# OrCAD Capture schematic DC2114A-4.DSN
size Custom; title: 42V, LOW I   QUAD OUTPUT TRIPLE MONOLITHIC; rev: 4; note: DC2114A; note: Q
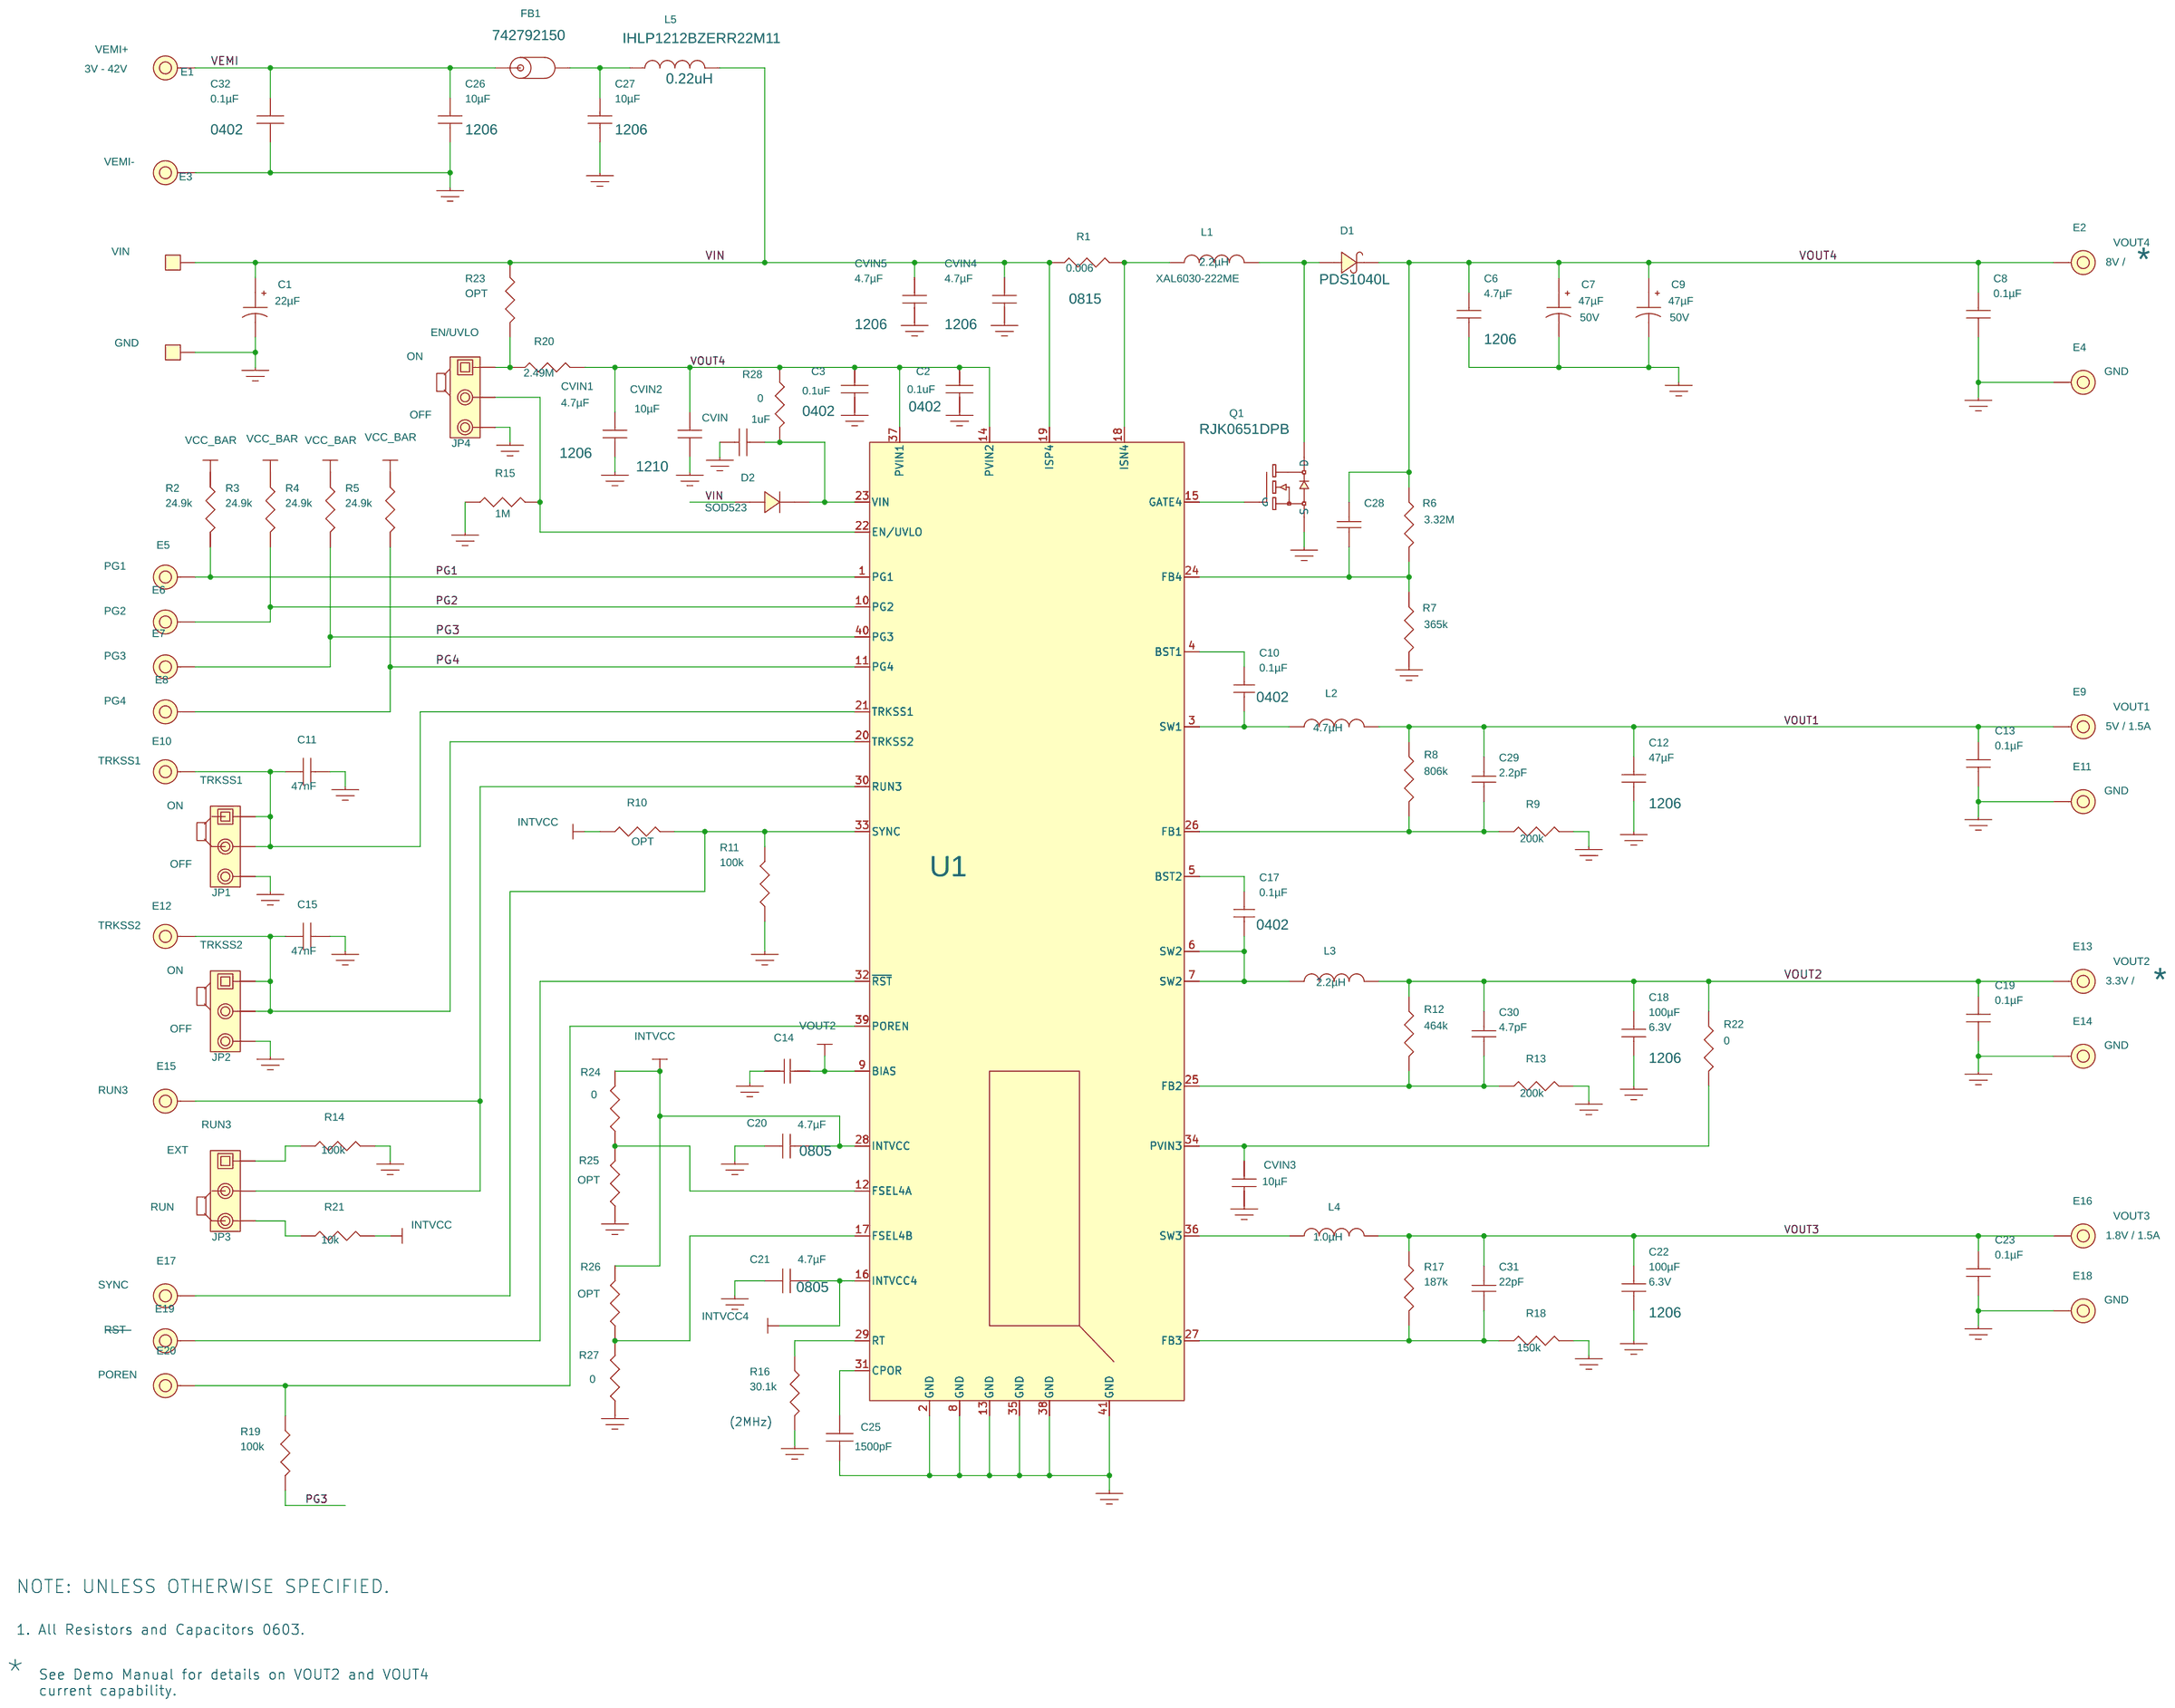
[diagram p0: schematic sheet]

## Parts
C1  22µF  [OSCON-CE-6.3]
C2  0.1uF  [0402]
C3  0.1uF  [0402]
C6  4.7µF  [1206]
C7  47µF  [OSCON-CE-6.3]
C8  0.1µF  [0603]
C9  47µF  [OSCON-CE-6.3]
C10  0.1µF  [0402]
C11  47nF  [0603]
C12  47µF  [1206]
C13  0.1µF  [0603]
C14  TBD  [0603]
C15  47nF  [0603]
C17  0.1µF  [0402]
C18  100µF  [1206]
C19  0.1µF  [0603]
C20  4.7µF  [0805]
C21  4.7µF  [0805]
C22  100µF  [1206]
C23  0.1µF  [0603]
C25  1500pF  [0603]
C26  10µF  [1206]
C27  10µF  [1206]
C28  TBD  [0603]
C29  2.2pF  [0603]
C30  4.7pF  [0603]
C31  22pF  [0603]
C32  0.1µF  [0402]
CVIN  1uF  [0603]
CVIN1  4.7µF  [1206]
CVIN2  10µF  [1210]
CVIN3  10µF  [0603]
CVIN4  4.7µF  [1206]
CVIN5  4.7µF  [1206]
D1  PDS1040L  [POWER-DI-5]
D2  SOD523  [SOD523]
E1  Testpoint  [0.094"]
E2  Testpoint  [0.094"]
E3  Testpoint  [0.094"]
E4  Testpoint  [0.094"]
E5  Testpoint  [0.094"]
E6  Testpoint  [0.094"]
E7  Testpoint  [0.094"]
E8  Testpoint  [0.094"]
E9  Testpoint  [0.094"]
E10  Testpoint  [0.094"]
E11  Testpoint  [0.094"]
E12  Testpoint  [0.094"]
E13  Testpoint  [0.094"]
E14  Testpoint  [0.094"]
E15  Testpoint  [0.094"]
E16  Testpoint  [0.094"]
E17  Testpoint  [0.094"]
E18  Testpoint  [0.094"]
E19  Testpoint  [0.094"]
E20  Testpoint  [0.094"]
FB1  742792150  [1206]
GND  Testpoint  [PAD30(SM)]
JP1  3 Pins 2mm Ctrs.  [Samtec\TMM-103-02-L-S]
JP2  3 Pins 2mm Ctrs.  [Samtec\TMM-103-02-L-S]
JP3  3 Pins 2mm Ctrs.  [Samtec\TMM-103-02-L-S]
JP4  3 Pins 2mm Ctrs.  [Samtec\TMM-103-02-L-S]
L1  2.2µH  [XAL6030-102ME-CBD/COILCRAFT]
L2  4.7µH  [IND-XAL50XX]
L3  2.2µH  [IND-XAL50XX]
L4  1.0µH  [NPIM42P]
L5  0.22uH  [IND-IHLP-1212AB-11]
Q1  60V/25A  [LFPAK/FET]
R1  0.006  [0815]
R2  24.9k  [0603]
R3  24.9k  [0603]
R4  24.9k  [0603]
R5  24.9k  [0603]
R6  3.32M  [0603]
R7  365k  [0603]
R8  806k  [0603]
R9  200k  [0603]
R10  TBD  [0603]
R11  100k  [0603]
R12  464k  [0603]
R13  200k  [0603]
R14  100k  [0603]
R15  1M  [0603]
R16  30.1k  [0603]
R17  187k  [0603]
R18  150k  [0603]
R19  100k  [0603]
R20  2.49M  [0603]
R21  10k  [0603]
R22  0  [0603]
R23  OPT  [0603]
R24  0  [0603]
R25  OPT  [0603]
R26  OPT  [0603]
R27  0  [0603]
R28  0  [0603]
U1  Buck Regulator  [QFN(40)(UJ)6MMX6MM]
VIN  Testpoint  [PAD30(SM)]
XJP1  2mm Ctrs.
XJP2  2mm Ctrs.
XJP3  2mm Ctrs.
XJP4  2mm Ctrs.

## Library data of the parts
C1 = 50CE22BSS: 4th Part Field: Sun Elect. Ind.
C2 C3 CVIN = C1608X5R1H105K
C6 = C3216X7R1H475KT_1
C7 = 50CE22BSS_2: 1st Part Field: 50V; 4th Part Field: Sun Elect. Ind.; 5TH PART FIELD: 50CE47BS
C8 C13 C19 C23 = GRM188R71H104KA93D
C9 = 50CE22BSS_1: 1st Part Field: 50V; 4th Part Field: Sun Elect. Ind.; 5TH PART FIELD: 25CE47BSS
C10 C17 = 06033C104KAT2A
C11 C15 = 06033C473MAT2A
C12 = GRM31CR61A476ME15L
C14 C28-C31 = CAP0603
C18 C22 = GRM31CR61A476ME15L: 1st Part Field: 6.3V
C20 C21 = GRM21BR71A475KA73K
C25 = 06033C221MAT2A: 2nd Part Field: 20%; 7th Part Field: Cap.,
C26 = C3216X7R1H475KT_5
C27 = C3216X7R1H475KT_3
C32 = CGA2B3X7R1H104K050BB
CVIN1 = C3216X7R1H475KT
CVIN2 = C3216X7R1H475KT_2
CVIN3 = GRM188R61E105KA12
CVIN4 = C3216X7R1H475KT_4
CVIN5 = C3216X7R1H475KT_6
D1 = B540C_0
D2 = diode-photo_2
E1 = MillMax-2501-2: 10th Part Field: 3V - 42V; 9th Part Field: VEMI+
E2 = MillMax-2501-2: 10th Part Field: 8V /; 11th Part Field: *; 9th Part Field: VOUT4
E3 = MillMax-2501-2: 9th Part Field: VEMI-
E4 E11 E14 E18 = MillMax-2501-2: 9th Part Field: GND
E5 = MillMax-2501-2: 9th Part Field: PG1
E6 = MillMax-2501-2: 9th Part Field: PG2
E7 = MillMax-2501-2: 9th Part Field: PG3
E8 = MillMax-2501-2: 9th Part Field: PG4
E9 = MillMax-2501-2: 10th Part Field: 5V / 1.5A; 9th Part Field: VOUT1
E10 = MillMax-2501-2: 9th Part Field: TRKSS1
E12 = MillMax-2501-2: 9th Part Field: TRKSS2
E13 = MillMax-2501-2: 10th Part Field: 3.3V /; 11th Part Field: *; 9th Part Field: VOUT2
E15 = MillMax-2501-2: 9th Part Field: RUN3
E16 = MillMax-2501-2: 10th Part Field: 1.8V / 1.5A; 9th Part Field: VOUT3
E17 = MillMax-2501-2: 9th Part Field: SYNC
E19 = MillMax-2501-2: 9th Part Field: RST
E20 = MillMax-2501-2: 9th Part Field: POREN
FB1 = MPZ2012S331AT000
GND = Testpad_075_smd: 9th Part Field: VEMI-
JP1 = Samtec_TMM-103-02-L-S: HEADER, 3PIN, 2mm; 11th Part Field: ON; 12th Part Field: TRKSS1; 9th Part Field: OFF; Part Number: SAMTEC TMM-103-02-L-S
JP2 = Samtec_TMM-103-02-L-S: HEADER, 3PIN, 2mm; 11th Part Field: ON; 12th Part Field: TRKSS2; 9th Part Field: OFF; Part Number: SAMTEC TMM-103-02-L-S
JP3 = Samtec_TMM-103-02-L-S: HEADER, 3PIN, 2mm; 11th Part Field: EXT; 12th Part Field: RUN3; 9th Part Field: RUN; Part Number: SAMTEC TMM-103-02-L-S
JP4 = Samtec_TMM-103-02-L-S: HEADER, 3PIN, 2mm; 11th Part Field: ON; 12th Part Field: EN/UVLO; 9th Part Field: OFF; Part Number: SAMTEC TMM-103-02-L-S
L1 = XAL6030-102MEC: 5th Part Field: XAL6030-222ME
L2 = NPIM52P4R7MTRF: 4TH PART FIELD: Coilcraft; 5TH PART FIELD: XAL5030-472ME
L3 = NPIM52P2R2MTRF: 4TH PART FIELD: Coilcraft; 5TH PART FIELD: XAL5030-222ME
L4 = NPIM42P1R0MTRF
L5 = IND_DO2010_COILCRAFT: 4th Part Field: VISHAY; Package Type: IHLP1212BZERR22M11
Q1 = RJK0651DPB-00-J5: 9th Part Field: RJK0651DPB
R1 = WSL-1206-0.300-1%: 5th Part Field: WSL-1206-3L000-1%
R2-R5 R9 R13-R15 R17 R19 R21 R23 = CRCW0603100KFKEA
R6 = CRCW06033M32FKEA
R7 = CRCW0603365KFKEA
R8 R28 = CRCW0603402KFKEA
R10 = RES0603: 6th Part Field: OPT
R11 R24-R27 = CRCW060310K0FKEA
R12 R22 = CRCW0603232KFKEA
R16 = CRCW060330K1FKEA
R18 = CRCW0603200KFKEA
R20 = CRCW06030000Z0EA
U1 = LT8603EUJ_21
VIN = Testpad_075_smd: 9th Part Field: VEMI+
XJP1-XJP4 = Samtec_2SN-BK-G: SHUNT, 2mm; Part Number: SAMTEC 2SN-BK-G

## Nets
GND: C1.2 C2.2 C3.2 C6.2 C7.2 C8.2 C9.2 C11.2 C12.2 C13.2 C14.2 C15.2 C18.2 C19.2 C20.1 C21.1 C22.2 C23.2 C25.2 C26.2 C27.2 C32.2 CVIN.2 CVIN1.2 CVIN2.2 CVIN3.2 CVIN4.2 CVIN5.2 E3.1 E4.1 E11.1 E14.1 E18.1 GND.1 JP1.3 JP2.3 JP4.3 Q1.S R7.2 R9.2 R11.2 R13.2 R14.1 R15.2 R16.1 R18.2 R25.2 R27.2 U1.2(GND) U1.8(GND) U1.13(GND) U1.35(GND) U1.38(GND) U1.41(GND)
VIN: C1.1 CVIN4.1 CVIN5.1 D2.2 L5.2 R1.1 R23.2 U1.19(ISP4) VIN.1
INTVCC: C20.2 R5.2 R10.2 R21.1 R24.1 R26.1 U1.28(INTVCC)
INTVCC4: C21.2 U1.16(INTVCC4)
PG1: E5.1 R2.1 U1.1(PG1)
PG2: E6.1 R3.1 U1.10(PG2)
PG3: E7.1 R4.1 R19.1 U1.40(PG3)
PG4: E8.1 R5.1 U1.11(PG4)
VEMI: C26.1 C32.1 E1.1 FB1.1
VOUT1: C12.1 C13.1 C29.1 E9.1 L2.2 R2.2 R3.2 R4.2 R8.1
VOUT2: C14.1 C18.1 C19.1 C30.1 E13.1 L3.2 R12.1 R22.1 U1.9(BIAS)
VOUT3: C22.1 C23.1 C31.1 E16.1 L4.2 R17.1
VOUT4: C2.1 C3.1 C6.1 C7.1 C8.1 C9.1 C28.1 CVIN1.1 CVIN2.1 D1.1(K) E2.1 R6.1 R20.2 R28.1 U1.14(PVIN2) U1.37(PVIN1)
N16779848: C29.2 R8.2 R9.1 U1.26(FB1)
N17136640: C30.2 R12.2 R13.1 U1.25(FB2)
N17145176: C31.2 R17.2 R18.1 U1.27(FB3)
N17145205: L4.1 U1.36(SW3)
N17499011: CVIN.1 D2.1 R28.2 U1.23(VIN)
N17499292: JP4.2 R15.1 U1.22(EN/UVLO)
N17515670: L1.1 R1.2 U1.18(ISN4)
N17532692: Q1.G U1.15(GATE4)
N17532977: D1.2(A) L1.2 Q1.D
N17542424: C28.2 R6.2 R7.1 U1.24(FB4)
N17562528: C10.1 U1.4(BST1)
N17562824: C10.2 L2.1 U1.3(SW1)
N17576862: C17.1 U1.5(BST2)
N17577439: C17.2 L3.1 U1.6(SW2) U1.7(SW2)
N17589060: CVIN3.1 R22.2 U1.34(PVIN3)
N17619961: JP3.1 R14.2
N17620267: E15.1 JP3.2 U1.30(RUN3)
N17662999: C11.1 E10.1 JP1.1 JP1.2 U1.21(TRKSS1)
N17664356: C15.1 E12.1 JP2.1 JP2.2 U1.20(TRKSS2)
N17673543: E17.1 R10.1 R11.1 U1.33(SYNC)
N17684327: C25.1 U1.31(CPOR)
N17687835: E20.1 R19.2 U1.39(POREN)
N17689154: E19.1 U1.32(~{RST})
N17691644: R16.2 U1.29(RT)
N17920642: JP4.1 R20.1 R23.1
N17963028: R24.2 R25.1 U1.12(FSEL4A)
N18017585: C27.1 FB1.2 L5.1
N18049683: R26.2 R27.1 U1.17(FSEL4B)
N18070227: JP3.3 R21.2

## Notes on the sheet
- (2MHz)
- NOTE: UNLESS OTHERWISE SPECIFIED.
- 1. All Resistors and Capacitors 0603.
- *
- See Demo Manual for details on VOUT2 and VOUT4
   current capability.
